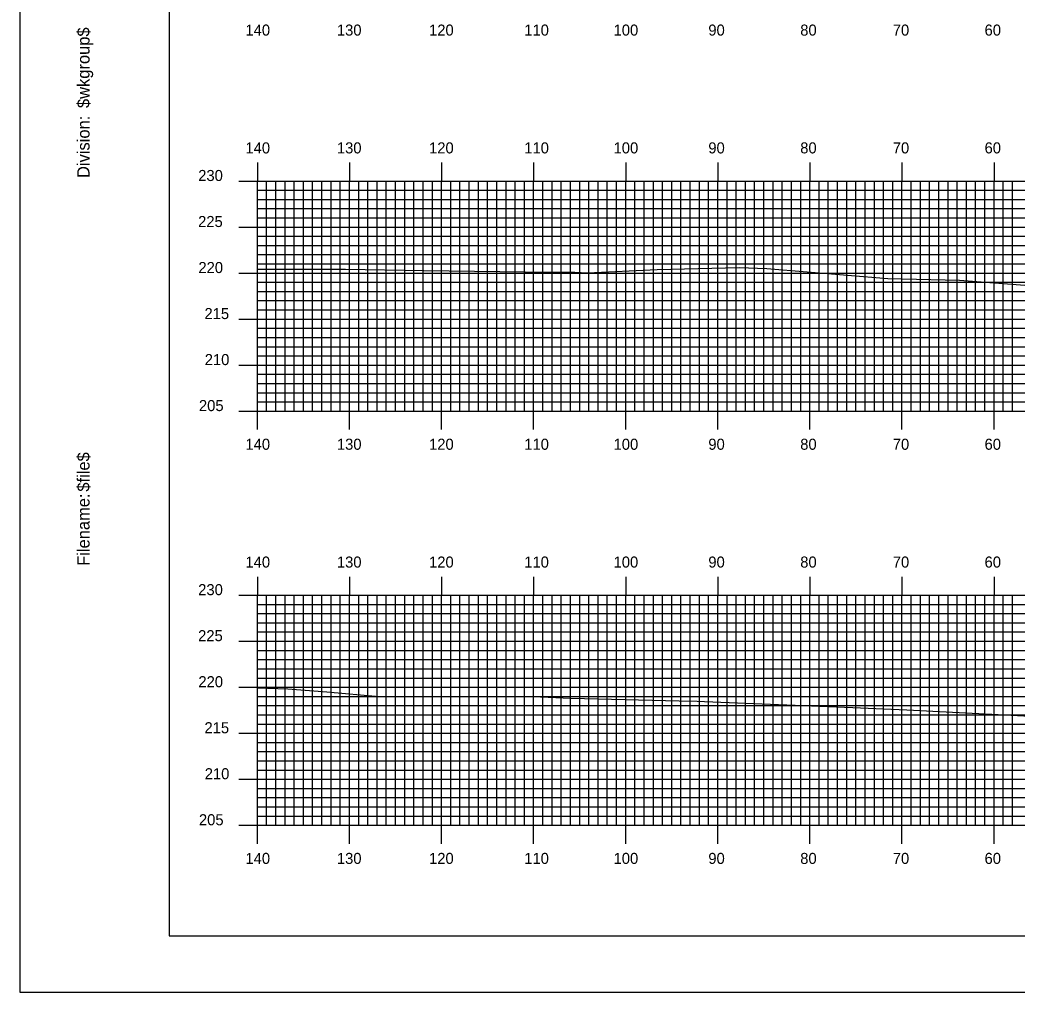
# Model space of a CAD drawing. Extents: x 1819637 to 1819981, y 442591 to 442811.
# Drawn here: x 1819637.4 to 1819745.7, y 442590.5 to 442696.2 of the extents above; entities that cross this region are included whole.
import ezdxf

# ---------------------------------------------------------------- set-up
doc = ezdxf.new("R2010")
doc.units = 0
for name, color, linetype in [('BORDER', 7, 'Continuous'), ('H_V ANNOTATION', 7, 'Continuous'), ('MAJOR', 7, 'Continuous'), ('MINOR', 7, 'Continuous'), ('PLOT BOUNDARY', 7, 'Continuous'), ('S_Roadway_Centerline', 7, 'Continuous')]:
    doc.layers.add(name, color=color, linetype=linetype)

msp = doc.modelspace()

# ---------------------------------------------------------------- linework, layer by layer
at = {"layer": 'BORDER'}
msp.add_lwpolyline([(1819653.58, 442596.67), (1819973.58, 442596.67), (1819973.58, 442806.67), (1819653.58, 442806.67)], close=True, dxfattribs=at)
at = {"layer": 'MAJOR'}
for p, q in [((1819663.18, 442680.67), (1819663.18, 442678.67)), ((1819673.18, 442680.67), (1819673.18, 442678.67)), ((1819683.18, 442680.67), (1819683.18, 442678.67)), ((1819693.18, 442680.67), (1819693.18, 442678.67)), ((1819703.18, 442680.67), (1819703.18, 442678.67)), ((1819713.18, 442680.67), (1819713.18, 442678.67)), ((1819723.18, 442680.67), (1819723.18, 442678.67)), ((1819733.18, 442680.67), (1819733.18, 442678.67)), ((1819743.18, 442680.67), (1819743.18, 442678.67)), ((1819661.17, 442678.67), (1819663.18, 442678.67)), ((1819663.18, 442678.67), (1819943.18, 442678.67)), ((1819663.18, 442653.67), (1819663.18, 442678.67)), ((1819663.18, 442653.67), (1819663.18, 442678.67)), ((1819663.18, 442678.67), (1819943.18, 442678.67)), ((1819673.18, 442653.67), (1819673.18, 442678.67)), ((1819683.18, 442653.67), (1819683.18, 442678.67)), ((1819693.18, 442653.67), (1819693.18, 442678.67)), ((1819703.18, 442653.67), (1819703.18, 442678.67)), ((1819713.18, 442653.67), (1819713.18, 442678.67)), ((1819723.18, 442653.67), (1819723.18, 442678.67)), ((1819733.18, 442653.67), (1819733.18, 442678.67)), ((1819743.18, 442653.67), (1819743.18, 442678.67)), ((1819661.17, 442673.67), (1819663.18, 442673.67)), ((1819663.18, 442673.67), (1819943.18, 442673.67)), ((1819661.17, 442668.67), (1819663.18, 442668.67)), ((1819663.18, 442668.67), (1819943.18, 442668.67)), ((1819661.17, 442663.67), (1819663.18, 442663.67)), ((1819663.18, 442663.67), (1819943.18, 442663.67)), ((1819661.17, 442658.67), (1819663.18, 442658.67)), ((1819663.18, 442658.67), (1819943.18, 442658.67)), ((1819661.17, 442653.67), (1819663.18, 442653.67)), ((1819663.18, 442653.67), (1819943.18, 442653.67)), ((1819663.18, 442653.67), (1819943.18, 442653.67)), ((1819663.18, 442651.66), (1819663.18, 442653.67)), ((1819673.18, 442651.66), (1819673.18, 442653.67)), ((1819683.18, 442651.66), (1819683.18, 442653.67)), ((1819693.18, 442651.66), (1819693.18, 442653.67)), ((1819703.18, 442651.66), (1819703.18, 442653.67)), ((1819713.18, 442651.66), (1819713.18, 442653.67)), ((1819723.18, 442651.66), (1819723.18, 442653.67)), ((1819733.18, 442651.66), (1819733.18, 442653.67)), ((1819743.18, 442651.66), (1819743.18, 442653.67)), ((1819663.18, 442635.67), (1819663.18, 442633.67)), ((1819673.18, 442635.67), (1819673.18, 442633.67)), ((1819683.18, 442635.67), (1819683.18, 442633.67)), ((1819693.18, 442635.67), (1819693.18, 442633.67)), ((1819703.18, 442635.67), (1819703.18, 442633.67)), ((1819713.18, 442635.67), (1819713.18, 442633.67)), ((1819723.18, 442635.67), (1819723.18, 442633.67)), ((1819733.18, 442635.67), (1819733.18, 442633.67)), ((1819743.18, 442635.67), (1819743.18, 442633.67)), ((1819661.17, 442633.67), (1819663.18, 442633.67)), ((1819663.18, 442633.67), (1819943.18, 442633.67)), ((1819663.18, 442608.67), (1819663.18, 442633.67)), ((1819663.18, 442608.67), (1819663.18, 442633.67)), ((1819663.18, 442633.67), (1819943.18, 442633.67)), ((1819673.18, 442608.67), (1819673.18, 442633.67)), ((1819683.18, 442608.67), (1819683.18, 442633.67)), ((1819693.18, 442608.67), (1819693.18, 442633.67)), ((1819703.18, 442608.67), (1819703.18, 442633.67)), ((1819713.18, 442608.67), (1819713.18, 442633.67)), ((1819723.18, 442608.67), (1819723.18, 442633.67)), ((1819733.18, 442608.67), (1819733.18, 442633.67)), ((1819743.18, 442608.67), (1819743.18, 442633.67)), ((1819661.17, 442628.67), (1819663.18, 442628.67)), ((1819663.18, 442628.67), (1819943.18, 442628.67)), ((1819661.17, 442623.67), (1819663.18, 442623.67)), ((1819663.18, 442623.67), (1819943.18, 442623.67)), ((1819661.17, 442618.67), (1819663.18, 442618.67)), ((1819663.18, 442618.67), (1819943.18, 442618.67)), ((1819661.17, 442613.67), (1819663.18, 442613.67)), ((1819663.18, 442613.67), (1819943.18, 442613.67)), ((1819661.17, 442608.67), (1819663.18, 442608.67)), ((1819663.18, 442608.67), (1819943.18, 442608.67)), ((1819663.18, 442608.67), (1819943.18, 442608.67)), ((1819663.18, 442606.66), (1819663.18, 442608.67)), ((1819673.18, 442606.66), (1819673.18, 442608.67)), ((1819683.18, 442606.66), (1819683.18, 442608.67)), ((1819693.18, 442606.66), (1819693.18, 442608.67)), ((1819703.18, 442606.66), (1819703.18, 442608.67)), ((1819713.18, 442606.66), (1819713.18, 442608.67)), ((1819723.18, 442606.66), (1819723.18, 442608.67)), ((1819733.18, 442606.66), (1819733.18, 442608.67)), ((1819743.18, 442606.66), (1819743.18, 442608.67))]:
    msp.add_line(p, q, dxfattribs=at)
at = {"layer": 'MINOR'}
for p, q in [((1819664.18, 442653.67), (1819664.18, 442678.67)), ((1819665.18, 442653.67), (1819665.18, 442678.67)), ((1819666.18, 442653.67), (1819666.18, 442678.67)), ((1819667.18, 442653.67), (1819667.18, 442678.67)), ((1819668.18, 442653.67), (1819668.18, 442678.67)), ((1819669.18, 442653.67), (1819669.18, 442678.67)), ((1819670.18, 442653.67), (1819670.18, 442678.67)), ((1819671.18, 442653.67), (1819671.18, 442678.67)), ((1819672.18, 442653.67), (1819672.18, 442678.67)), ((1819674.18, 442653.67), (1819674.18, 442678.67)), ((1819675.18, 442653.67), (1819675.18, 442678.67)), ((1819676.18, 442653.67), (1819676.18, 442678.67)), ((1819677.18, 442653.67), (1819677.18, 442678.67)), ((1819678.18, 442653.67), (1819678.18, 442678.67)), ((1819679.18, 442653.67), (1819679.18, 442678.67)), ((1819680.18, 442653.67), (1819680.18, 442678.67)), ((1819681.18, 442653.67), (1819681.18, 442678.67)), ((1819682.18, 442653.67), (1819682.18, 442678.67)), ((1819684.18, 442653.67), (1819684.18, 442678.67)), ((1819685.18, 442653.67), (1819685.18, 442678.67)), ((1819686.18, 442653.67), (1819686.18, 442678.67)), ((1819687.18, 442653.67), (1819687.18, 442678.67)), ((1819688.18, 442653.67), (1819688.18, 442678.67)), ((1819689.18, 442653.67), (1819689.18, 442678.67)), ((1819690.18, 442653.67), (1819690.18, 442678.67)), ((1819691.18, 442653.67), (1819691.18, 442678.67)), ((1819692.18, 442653.67), (1819692.18, 442678.67)), ((1819694.18, 442653.67), (1819694.18, 442678.67)), ((1819695.18, 442653.67), (1819695.18, 442678.67)), ((1819696.18, 442653.67), (1819696.18, 442678.67)), ((1819697.18, 442653.67), (1819697.18, 442678.67)), ((1819698.18, 442653.67), (1819698.18, 442678.67)), ((1819699.18, 442653.67), (1819699.18, 442678.67)), ((1819700.18, 442653.67), (1819700.18, 442678.67)), ((1819701.18, 442653.67), (1819701.18, 442678.67)), ((1819702.18, 442653.67), (1819702.18, 442678.67)), ((1819704.18, 442653.67), (1819704.18, 442678.67)), ((1819705.18, 442653.67), (1819705.18, 442678.67)), ((1819706.18, 442653.67), (1819706.18, 442678.67)), ((1819707.18, 442653.67), (1819707.18, 442678.67)), ((1819708.18, 442653.67), (1819708.18, 442678.67)), ((1819709.18, 442653.67), (1819709.18, 442678.67)), ((1819710.18, 442653.67), (1819710.18, 442678.67)), ((1819711.18, 442653.67), (1819711.18, 442678.67)), ((1819712.18, 442653.67), (1819712.18, 442678.67)), ((1819714.18, 442653.67), (1819714.18, 442678.67)), ((1819715.18, 442653.67), (1819715.18, 442678.67)), ((1819716.18, 442653.67), (1819716.18, 442678.67)), ((1819717.18, 442653.67), (1819717.18, 442678.67)), ((1819718.18, 442653.67), (1819718.18, 442678.67)), ((1819719.18, 442653.67), (1819719.18, 442678.67)), ((1819720.18, 442653.67), (1819720.18, 442678.67)), ((1819721.18, 442653.67), (1819721.18, 442678.67)), ((1819722.18, 442653.67), (1819722.18, 442678.67)), ((1819724.18, 442653.67), (1819724.18, 442678.67)), ((1819725.18, 442653.67), (1819725.18, 442678.67)), ((1819726.18, 442653.67), (1819726.18, 442678.67)), ((1819727.18, 442653.67), (1819727.18, 442678.67)), ((1819728.18, 442653.67), (1819728.18, 442678.67)), ((1819729.18, 442653.67), (1819729.18, 442678.67)), ((1819730.18, 442653.67), (1819730.18, 442678.67)), ((1819731.18, 442653.67), (1819731.18, 442678.67)), ((1819732.18, 442653.67), (1819732.18, 442678.67)), ((1819734.18, 442653.67), (1819734.18, 442678.67)), ((1819735.18, 442653.67), (1819735.18, 442678.67)), ((1819736.18, 442653.67), (1819736.18, 442678.67)), ((1819737.18, 442653.67), (1819737.18, 442678.67)), ((1819738.18, 442653.67), (1819738.18, 442678.67)), ((1819739.18, 442653.67), (1819739.18, 442678.67)), ((1819740.18, 442653.67), (1819740.18, 442678.67)), ((1819741.18, 442653.67), (1819741.18, 442678.67)), ((1819742.18, 442653.67), (1819742.18, 442678.67)), ((1819744.18, 442653.67), (1819744.18, 442678.67)), ((1819745.18, 442653.67), (1819745.18, 442678.67)), ((1819663.18, 442677.67), (1819943.18, 442677.67)), ((1819663.18, 442677.67), (1819665.18, 442677.67)), ((1819663.18, 442676.67), (1819943.18, 442676.67)), ((1819663.18, 442676.67), (1819665.18, 442676.67)), ((1819663.18, 442675.67), (1819943.18, 442675.67)), ((1819663.18, 442675.67), (1819665.18, 442675.67)), ((1819663.18, 442674.67), (1819943.18, 442674.67)), ((1819663.18, 442674.67), (1819665.18, 442674.67)), ((1819663.18, 442672.67), (1819943.18, 442672.67)), ((1819663.18, 442672.67), (1819665.18, 442672.67)), ((1819663.18, 442671.67), (1819943.18, 442671.67)), ((1819663.18, 442671.67), (1819665.18, 442671.67)), ((1819663.18, 442670.67), (1819943.18, 442670.67)), ((1819663.18, 442670.67), (1819665.18, 442670.67)), ((1819663.18, 442669.67), (1819943.18, 442669.67)), ((1819663.18, 442669.67), (1819665.18, 442669.67)), ((1819663.18, 442667.67), (1819943.18, 442667.67)), ((1819663.18, 442667.67), (1819665.18, 442667.67)), ((1819663.18, 442666.67), (1819943.18, 442666.67)), ((1819663.18, 442666.67), (1819665.18, 442666.67)), ((1819663.18, 442665.67), (1819943.18, 442665.67)), ((1819663.18, 442665.67), (1819665.18, 442665.67)), ((1819663.18, 442664.67), (1819943.18, 442664.67)), ((1819663.18, 442664.67), (1819665.18, 442664.67)), ((1819663.18, 442662.67), (1819943.18, 442662.67)), ((1819663.18, 442662.67), (1819665.18, 442662.67)), ((1819663.18, 442661.67), (1819943.18, 442661.67)), ((1819663.18, 442661.67), (1819665.18, 442661.67)), ((1819663.18, 442660.67), (1819943.18, 442660.67)), ((1819663.18, 442660.67), (1819665.18, 442660.67)), ((1819663.18, 442659.67), (1819943.18, 442659.67)), ((1819663.18, 442659.67), (1819665.18, 442659.67)), ((1819663.18, 442657.67), (1819943.18, 442657.67)), ((1819663.18, 442657.67), (1819665.18, 442657.67)), ((1819663.18, 442656.67), (1819943.18, 442656.67)), ((1819663.18, 442656.67), (1819665.18, 442656.67)), ((1819663.18, 442655.67), (1819943.18, 442655.67)), ((1819663.18, 442655.67), (1819665.18, 442655.67)), ((1819663.18, 442654.67), (1819943.18, 442654.67)), ((1819663.18, 442654.67), (1819665.18, 442654.67)), ((1819664.18, 442608.67), (1819664.18, 442633.67)), ((1819665.18, 442608.67), (1819665.18, 442633.67)), ((1819666.18, 442608.67), (1819666.18, 442633.67)), ((1819667.18, 442608.67), (1819667.18, 442633.67)), ((1819668.18, 442608.67), (1819668.18, 442633.67)), ((1819669.18, 442608.67), (1819669.18, 442633.67)), ((1819670.18, 442608.67), (1819670.18, 442633.67)), ((1819671.18, 442608.67), (1819671.18, 442633.67)), ((1819672.18, 442608.67), (1819672.18, 442633.67)), ((1819674.18, 442608.67), (1819674.18, 442633.67)), ((1819675.18, 442608.67), (1819675.18, 442633.67)), ((1819676.18, 442608.67), (1819676.18, 442633.67)), ((1819677.18, 442608.67), (1819677.18, 442633.67)), ((1819678.18, 442608.67), (1819678.18, 442633.67)), ((1819679.18, 442608.67), (1819679.18, 442633.67)), ((1819680.18, 442608.67), (1819680.18, 442633.67)), ((1819681.18, 442608.67), (1819681.18, 442633.67)), ((1819682.18, 442608.67), (1819682.18, 442633.67)), ((1819684.18, 442608.67), (1819684.18, 442633.67)), ((1819685.18, 442608.67), (1819685.18, 442633.67)), ((1819686.18, 442608.67), (1819686.18, 442633.67)), ((1819687.18, 442608.67), (1819687.18, 442633.67)), ((1819688.18, 442608.67), (1819688.18, 442633.67)), ((1819689.18, 442608.67), (1819689.18, 442633.67)), ((1819690.18, 442608.67), (1819690.18, 442633.67)), ((1819691.18, 442608.67), (1819691.18, 442633.67)), ((1819692.18, 442608.67), (1819692.18, 442633.67)), ((1819694.18, 442608.67), (1819694.18, 442633.67)), ((1819695.18, 442608.67), (1819695.18, 442633.67)), ((1819696.18, 442608.67), (1819696.18, 442633.67)), ((1819697.18, 442608.67), (1819697.18, 442633.67)), ((1819698.18, 442608.67), (1819698.18, 442633.67)), ((1819699.18, 442608.67), (1819699.18, 442633.67)), ((1819700.18, 442608.67), (1819700.18, 442633.67)), ((1819701.18, 442608.67), (1819701.18, 442633.67)), ((1819702.18, 442608.67), (1819702.18, 442633.67)), ((1819704.18, 442608.67), (1819704.18, 442633.67)), ((1819705.18, 442608.67), (1819705.18, 442633.67)), ((1819706.18, 442608.67), (1819706.18, 442633.67)), ((1819707.18, 442608.67), (1819707.18, 442633.67)), ((1819708.18, 442608.67), (1819708.18, 442633.67)), ((1819709.18, 442608.67), (1819709.18, 442633.67)), ((1819710.18, 442608.67), (1819710.18, 442633.67)), ((1819711.18, 442608.67), (1819711.18, 442633.67)), ((1819712.18, 442608.67), (1819712.18, 442633.67)), ((1819714.18, 442608.67), (1819714.18, 442633.67)), ((1819715.18, 442608.67), (1819715.18, 442633.67)), ((1819716.18, 442608.67), (1819716.18, 442633.67)), ((1819717.18, 442608.67), (1819717.18, 442633.67)), ((1819718.18, 442608.67), (1819718.18, 442633.67)), ((1819719.18, 442608.67), (1819719.18, 442633.67)), ((1819720.18, 442608.67), (1819720.18, 442633.67)), ((1819721.18, 442608.67), (1819721.18, 442633.67)), ((1819722.18, 442608.67), (1819722.18, 442633.67)), ((1819724.18, 442608.67), (1819724.18, 442633.67)), ((1819725.18, 442608.67), (1819725.18, 442633.67)), ((1819726.18, 442608.67), (1819726.18, 442633.67)), ((1819727.18, 442608.67), (1819727.18, 442633.67)), ((1819728.18, 442608.67), (1819728.18, 442633.67)), ((1819729.18, 442608.67), (1819729.18, 442633.67)), ((1819730.18, 442608.67), (1819730.18, 442633.67)), ((1819731.18, 442608.67), (1819731.18, 442633.67)), ((1819732.18, 442608.67), (1819732.18, 442633.67)), ((1819734.18, 442608.67), (1819734.18, 442633.67)), ((1819735.18, 442608.67), (1819735.18, 442633.67)), ((1819736.18, 442608.67), (1819736.18, 442633.67)), ((1819737.18, 442608.67), (1819737.18, 442633.67)), ((1819738.18, 442608.67), (1819738.18, 442633.67)), ((1819739.18, 442608.67), (1819739.18, 442633.67)), ((1819740.18, 442608.67), (1819740.18, 442633.67)), ((1819741.18, 442608.67), (1819741.18, 442633.67)), ((1819742.18, 442608.67), (1819742.18, 442633.67)), ((1819744.18, 442608.67), (1819744.18, 442633.67)), ((1819745.18, 442608.67), (1819745.18, 442633.67)), ((1819663.18, 442632.67), (1819943.18, 442632.67)), ((1819663.18, 442632.67), (1819665.18, 442632.67)), ((1819663.18, 442631.67), (1819943.18, 442631.67)), ((1819663.18, 442631.67), (1819665.18, 442631.67)), ((1819663.18, 442630.67), (1819943.18, 442630.67)), ((1819663.18, 442630.67), (1819665.18, 442630.67)), ((1819663.18, 442629.67), (1819943.18, 442629.67)), ((1819663.18, 442629.67), (1819665.18, 442629.67)), ((1819663.18, 442627.67), (1819943.18, 442627.67)), ((1819663.18, 442627.67), (1819665.18, 442627.67)), ((1819663.18, 442626.67), (1819943.18, 442626.67)), ((1819663.18, 442626.67), (1819665.18, 442626.67)), ((1819663.18, 442625.67), (1819943.18, 442625.67)), ((1819663.18, 442625.67), (1819665.18, 442625.67)), ((1819663.18, 442624.67), (1819943.18, 442624.67)), ((1819663.18, 442624.67), (1819665.18, 442624.67)), ((1819663.18, 442622.67), (1819943.18, 442622.67)), ((1819663.18, 442622.67), (1819665.18, 442622.67)), ((1819663.18, 442621.67), (1819943.18, 442621.67)), ((1819663.18, 442621.67), (1819665.18, 442621.67)), ((1819663.18, 442620.67), (1819943.18, 442620.67)), ((1819663.18, 442620.67), (1819665.18, 442620.67)), ((1819663.18, 442619.67), (1819943.18, 442619.67)), ((1819663.18, 442619.67), (1819665.18, 442619.67)), ((1819663.18, 442617.67), (1819943.18, 442617.67)), ((1819663.18, 442617.67), (1819665.18, 442617.67)), ((1819663.18, 442616.67), (1819943.18, 442616.67)), ((1819663.18, 442616.67), (1819665.18, 442616.67)), ((1819663.18, 442615.67), (1819943.18, 442615.67)), ((1819663.18, 442615.67), (1819665.18, 442615.67)), ((1819663.18, 442614.67), (1819943.18, 442614.67)), ((1819663.18, 442614.67), (1819665.18, 442614.67)), ((1819663.18, 442612.67), (1819943.18, 442612.67)), ((1819663.18, 442612.67), (1819665.18, 442612.67)), ((1819663.18, 442611.67), (1819943.18, 442611.67)), ((1819663.18, 442611.67), (1819665.18, 442611.67)), ((1819663.18, 442610.67), (1819943.18, 442610.67)), ((1819663.18, 442610.67), (1819665.18, 442610.67)), ((1819663.18, 442609.67), (1819943.18, 442609.67)), ((1819663.18, 442609.67), (1819665.18, 442609.67))]:
    msp.add_line(p, q, dxfattribs=at)
at = {"layer": 'PLOT BOUNDARY'}
msp.add_lwpolyline([(1819637.39, 442590.55), (1819977.39, 442590.55), (1819977.39, 442810.55), (1819637.39, 442810.55)], close=True, dxfattribs=at)
at = {"layer": 'S_Roadway_Centerline'}
for points in [[(1819663.18, 442669.11), (1819663.36, 442669.1), (1819672.73, 442669.08), (1819681.25, 442668.96), (1819695, 442668.76), (1819697.67, 442668.76), (1819699.01, 442668.7), (1819706.58, 442669.07), (1819715.51, 442669.29), (1819718.52, 442669.16), (1819731.65, 442668.07), (1819739.41, 442667.9), (1819762.61, 442666.13), (1819764.92, 442665.92), (1819770.34, 442665.53), (1819782.62, 442664.8), (1819788.26, 442664.67), (1819798.98, 442664.58), (1819805.45, 442664.38), (1819817.9, 442664.3), (1819821.92, 442664.24), (1819850.87, 442663.63), (1819860.19, 442663.38)], [(1819663.18, 442623.62), (1819666.48, 442623.49), (1819670.71, 442623.16), (1819676.4, 442622.65), (1819688.03, 442622.65), (1819693.91, 442622.62), (1819697.22, 442622.47), (1819708.98, 442622.2), (1819710.94, 442622.14), (1819711.72, 442622.12), (1819727.84, 442621.48), (1819733.69, 442621.2), (1819744.35, 442620.68), (1819749.16, 442620.4), (1819761.15, 442619.9), (1819777.48, 442619.58), (1819779.45, 442619.55), (1819808.13, 442618.86), (1819817.28, 442618.63), (1819845.46, 442618.36), (1819846.85, 442618.34), (1819857.51, 442618.33)]]:
    msp.add_lwpolyline(points, dxfattribs=at)

# ---------------------------------------------------------------- texts
at = {"layer": 'BORDER'}
for s, p in [('$wkgroup$', (1819644.95, 442686.6)), ('Division:', (1819644.95, 442679)), ('$file$', (1819644.95, 442644.92)), ('Filename:', (1819644.95, 442636.86))]:
    msp.add_text(s, height=1.339, rotation=90, dxfattribs=at).set_placement(p)
at = {"layer": 'H_V ANNOTATION'}
for s, p in [('140', (1819661.88, 442694.47)), ('130', (1819671.81, 442694.47)), ('120', (1819681.82, 442694.47)), ('110', (1819692.16, 442694.47)), ('100', (1819701.86, 442694.47)), ('90', (1819712.15, 442694.47)), ('80', (1819722.13, 442694.47)), ('70', (1819732.18, 442694.47)), ('60', (1819742.15, 442694.47)), ('140', (1819661.88, 442681.67)), ('130', (1819671.81, 442681.67)), ('120', (1819681.82, 442681.67)), ('110', (1819692.16, 442681.67)), ('100', (1819701.86, 442681.67)), ('90', (1819712.15, 442681.67)), ('80', (1819722.13, 442681.67)), ('70', (1819732.18, 442681.67)), ('60', (1819742.15, 442681.67)), ('230', (1819656.75, 442678.67)), ('225', (1819656.74, 442673.67)), ('220', (1819656.77, 442668.67)), ('215', (1819657.43, 442663.67)), ('210', (1819657.46, 442658.67)), ('205', (1819656.83, 442653.67)), ('140', (1819661.88, 442649.47)), ('130', (1819671.81, 442649.47)), ('120', (1819681.82, 442649.47)), ('110', (1819692.16, 442649.47)), ('100', (1819701.86, 442649.47)), ('90', (1819712.15, 442649.47)), ('80', (1819722.13, 442649.47)), ('70', (1819732.18, 442649.47)), ('60', (1819742.15, 442649.47)), ('140', (1819661.88, 442636.67)), ('130', (1819671.81, 442636.67)), ('120', (1819681.82, 442636.67)), ('110', (1819692.16, 442636.67)), ('100', (1819701.86, 442636.67)), ('90', (1819712.15, 442636.67)), ('80', (1819722.13, 442636.67)), ('70', (1819732.18, 442636.67)), ('60', (1819742.15, 442636.67)), ('230', (1819656.75, 442633.67)), ('225', (1819656.74, 442628.67)), ('220', (1819656.77, 442623.67)), ('215', (1819657.43, 442618.67)), ('210', (1819657.46, 442613.67)), ('205', (1819656.83, 442608.67)), ('140', (1819661.88, 442604.47)), ('130', (1819671.81, 442604.47)), ('120', (1819681.82, 442604.47)), ('110', (1819692.16, 442604.47)), ('100', (1819701.86, 442604.47)), ('90', (1819712.15, 442604.47)), ('80', (1819722.13, 442604.47)), ('70', (1819732.18, 442604.47)), ('60', (1819742.15, 442604.47))]:
    msp.add_text(s, height=1.2, dxfattribs=at).set_placement(p)
at = {"layer": 'MAJOR'}
for p in [(1819663.17, 442653.67), (1819663.17, 442608.67)]:
    msp.add_text('-', height=0.012, dxfattribs=at).set_placement(p)

doc.saveas('drawing.dxf')
